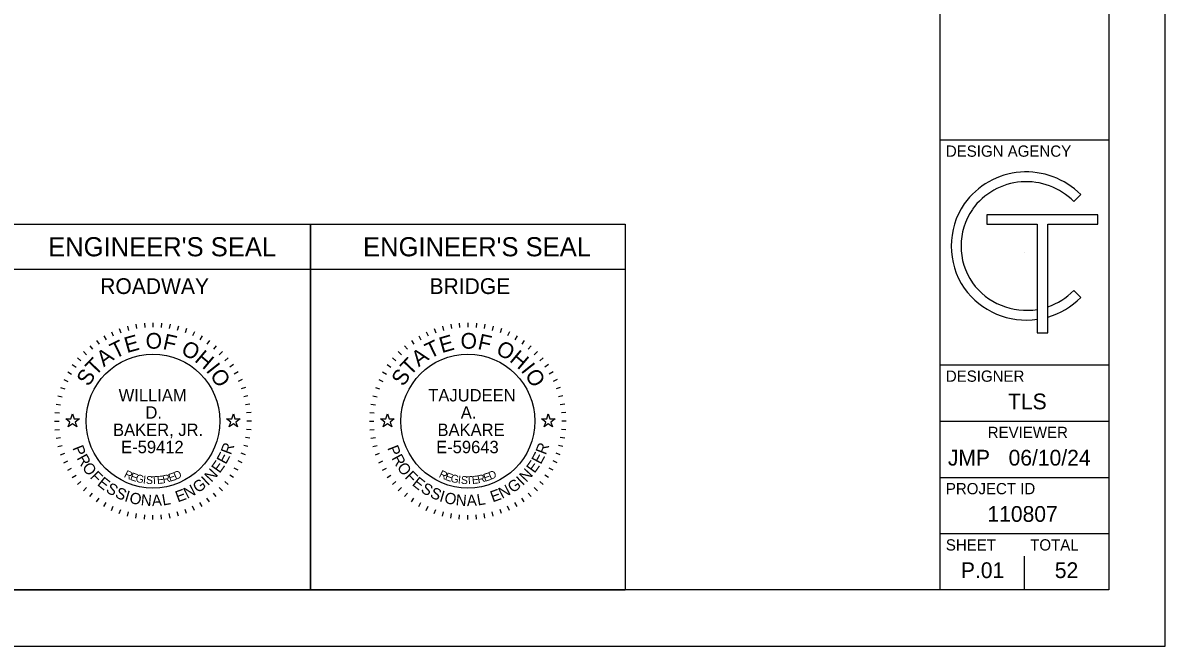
# Model space of a CAD drawing. Extents: x -5.4 to 71.3, y -12 to 22.
# Drawn here: x 23.84 to 34, y 0 to 5.54 of the extents above; entities that cross this region are included whole.
import ezdxf

# ---------------------------------------------------------------- set-up
doc = ezdxf.new("R2010")
doc.units = 0
for name, color, linetype in [('Default', 7, 'Continuous'), ('SH_Border', 7, 'Continuous'), ('SH_Cut_Line', 7, 'Continuous'), ('SH_Data', 7, 'Continuous'), ('SH_Text', 7, 'Continuous')]:
    doc.layers.add(name, color=color, linetype=linetype)

msp = doc.modelspace()

# ---------------------------------------------------------------- linework, layer by layer
at = {"layer": 'Default'}
for points in [[(24.224, 2.02), (24.271, 2.02), (24.285, 2.065), (24.299, 2.02), (24.346, 2.02), (24.308, 1.992), (24.323, 1.948), (24.285, 1.975), (24.247, 1.948), (24.262, 1.992)], [(25.654, 2.02), (25.701, 2.02), (25.715, 2.065), (25.729, 2.02), (25.776, 2.02), (25.738, 1.992), (25.753, 1.948), (25.715, 1.975), (25.677, 1.948), (25.692, 1.992)], [(27.024, 2.02), (27.071, 2.02), (27.085, 2.065), (27.099, 2.02), (27.146, 2.02), (27.108, 1.992), (27.123, 1.948), (27.085, 1.975), (27.047, 1.948), (27.062, 1.992)], [(28.454, 2.02), (28.501, 2.02), (28.515, 2.065), (28.529, 2.02), (28.576, 2.02), (28.538, 1.992), (28.553, 1.948), (28.515, 1.975), (28.477, 1.948), (28.492, 1.992)]]:
    msp.add_lwpolyline(points, close=True, dxfattribs=at)
at = {"layer": 'SH_Border'}
for p, q in [((32, 0.5), (32, 21.5)), ((32, 4.5), (33.5, 4.5)), ((32, 2.5), (33.5, 2.5)), ((32, 2), (33.5, 2)), ((32, 1.5), (33.5, 1.5)), ((32, 1), (33.5, 1))]:
    msp.add_line(p, q, dxfattribs=at)
msp.add_lwpolyline([(1.5, 21.5), (33.5, 21.5), (33.5, 0.5), (1.5, 0.5)], close=True, dxfattribs=at)
at = {"layer": 'SH_Cut_Line'}
msp.add_lwpolyline([(0, 0), (34, 0), (34, 22), (0, 22)], close=True, dxfattribs=at)
at = {"layer": 'SH_Data'}
for p, q in [((23.6, 3.75), (26.4, 3.75)), ((26.4, 3.75), (26.4, 0.5)), ((26.4, 0.5), (26.4, 3.75)), ((26.4, 3.75), (29.2, 3.75)), ((29.2, 3.75), (29.2, 0.5)), ((32.75, 3.5), (32.75, 3.5)), ((23.6, 3.35), (26.4, 3.35)), ((26.4, 3.35), (29.2, 3.35)), ((24.774, 2.845), (24.784, 2.807)), ((24.848, 2.862), (24.855, 2.822)), ((24.924, 2.872), (24.927, 2.832)), ((25, 2.875), (25, 2.835)), ((25.076, 2.872), (25.073, 2.832)), ((25.152, 2.862), (25.145, 2.822)), ((25.226, 2.845), (25.216, 2.807)), ((27.574, 2.845), (27.584, 2.807)), ((27.648, 2.862), (27.655, 2.822)), ((27.724, 2.872), (27.727, 2.832)), ((27.8, 2.875), (27.8, 2.835)), ((27.876, 2.872), (27.873, 2.832)), ((27.952, 2.862), (27.945, 2.822)), ((28.026, 2.845), (28.016, 2.807)), ((24.563, 2.758), (24.583, 2.723)), ((24.63, 2.793), (24.647, 2.757)), ((24.701, 2.822), (24.714, 2.785)), ((25.299, 2.822), (25.286, 2.785)), ((25.37, 2.793), (25.353, 2.757)), ((25.437, 2.758), (25.417, 2.723)), ((27.363, 2.758), (27.383, 2.723)), ((27.43, 2.793), (27.447, 2.757)), ((27.501, 2.822), (27.514, 2.785)), ((28.099, 2.822), (28.086, 2.785)), ((28.17, 2.793), (28.153, 2.757)), ((28.237, 2.758), (28.217, 2.723)), ((24.438, 2.67), (24.463, 2.64)), ((24.498, 2.717), (24.521, 2.684)), ((25.502, 2.717), (25.479, 2.684)), ((25.562, 2.67), (25.537, 2.64)), ((27.238, 2.67), (27.263, 2.64)), ((27.298, 2.717), (27.321, 2.684)), ((28.302, 2.717), (28.279, 2.684)), ((28.362, 2.67), (28.337, 2.64)), ((24.33, 2.562), (24.36, 2.537)), ((24.381, 2.619), (24.41, 2.59)), ((25.619, 2.619), (25.59, 2.59)), ((25.67, 2.562), (25.64, 2.537)), ((27.13, 2.562), (27.16, 2.537)), ((27.181, 2.619), (27.21, 2.59)), ((28.419, 2.619), (28.39, 2.59)), ((28.47, 2.562), (28.44, 2.537)), ((24.283, 2.502), (24.316, 2.479)), ((25.717, 2.502), (25.684, 2.479)), ((27.083, 2.502), (27.116, 2.479)), ((28.517, 2.502), (28.484, 2.479)), ((24.207, 2.37), (24.243, 2.353)), ((24.242, 2.438), (24.277, 2.418)), ((25.758, 2.438), (25.723, 2.418)), ((25.793, 2.37), (25.757, 2.353)), ((27.007, 2.37), (27.043, 2.353)), ((27.042, 2.438), (27.077, 2.418)), ((28.558, 2.438), (28.523, 2.418)), ((28.593, 2.37), (28.557, 2.353)), ((24.178, 2.299), (24.215, 2.286)), ((25.822, 2.299), (25.785, 2.286)), ((26.978, 2.299), (27.015, 2.286)), ((28.622, 2.299), (28.585, 2.286)), ((24.138, 2.152), (24.178, 2.145)), ((24.155, 2.226), (24.193, 2.216)), ((25.845, 2.226), (25.807, 2.216)), ((25.862, 2.152), (25.822, 2.145)), ((26.938, 2.152), (26.978, 2.145)), ((26.955, 2.226), (26.993, 2.216)), ((28.645, 2.226), (28.607, 2.216)), ((28.662, 2.152), (28.622, 2.145)), ((24.128, 2.076), (24.168, 2.073)), ((25.872, 2.076), (25.832, 2.073)), ((26.928, 2.076), (26.968, 2.073)), ((28.672, 2.076), (28.632, 2.073)), ((24.125, 2), (24.165, 2)), ((25.875, 2), (25.835, 2)), ((26.925, 2), (26.965, 2)), ((28.675, 2), (28.635, 2)), ((24.128, 1.924), (24.168, 1.927)), ((24.138, 1.848), (24.178, 1.855)), ((25.862, 1.848), (25.822, 1.855)), ((25.872, 1.924), (25.832, 1.927)), ((26.928, 1.924), (26.968, 1.927)), ((26.938, 1.848), (26.978, 1.855)), ((28.662, 1.848), (28.622, 1.855)), ((28.672, 1.924), (28.632, 1.927)), ((24.155, 1.774), (24.193, 1.784)), ((25.845, 1.774), (25.807, 1.784)), ((26.955, 1.774), (26.993, 1.784)), ((28.645, 1.774), (28.607, 1.784)), ((24.178, 1.701), (24.215, 1.714)), ((24.207, 1.63), (24.243, 1.647)), ((25.793, 1.63), (25.757, 1.647)), ((25.822, 1.701), (25.785, 1.714)), ((26.978, 1.701), (27.015, 1.714)), ((27.007, 1.63), (27.043, 1.647)), ((28.593, 1.63), (28.557, 1.647)), ((28.622, 1.701), (28.585, 1.714)), ((24.242, 1.563), (24.277, 1.583)), ((25.758, 1.563), (25.723, 1.583)), ((27.042, 1.563), (27.077, 1.583)), ((28.558, 1.563), (28.523, 1.583)), ((24.283, 1.498), (24.316, 1.521)), ((24.33, 1.438), (24.36, 1.463)), ((25.67, 1.438), (25.64, 1.463)), ((25.717, 1.498), (25.684, 1.521)), ((27.083, 1.498), (27.116, 1.521)), ((27.13, 1.438), (27.16, 1.463)), ((28.47, 1.438), (28.44, 1.463)), ((28.517, 1.498), (28.484, 1.521)), ((24.381, 1.381), (24.41, 1.41)), ((24.438, 1.33), (24.463, 1.36)), ((25.562, 1.33), (25.537, 1.36)), ((25.619, 1.381), (25.59, 1.41)), ((27.181, 1.381), (27.21, 1.41)), ((27.238, 1.33), (27.263, 1.36)), ((28.362, 1.33), (28.337, 1.36)), ((28.419, 1.381), (28.39, 1.41)), ((24.498, 1.283), (24.521, 1.316)), ((24.563, 1.242), (24.583, 1.277)), ((24.63, 1.207), (24.647, 1.243)), ((25.37, 1.207), (25.353, 1.243)), ((25.437, 1.242), (25.417, 1.277)), ((25.502, 1.283), (25.479, 1.316)), ((27.298, 1.283), (27.321, 1.316)), ((27.363, 1.242), (27.383, 1.277)), ((27.43, 1.207), (27.447, 1.243)), ((28.17, 1.207), (28.153, 1.243)), ((28.237, 1.242), (28.217, 1.277)), ((28.302, 1.283), (28.279, 1.316)), ((24.701, 1.178), (24.714, 1.215)), ((24.774, 1.155), (24.784, 1.193)), ((24.848, 1.138), (24.855, 1.178)), ((24.924, 1.128), (24.927, 1.168)), ((25, 1.125), (25, 1.165)), ((25.076, 1.128), (25.073, 1.168)), ((25.152, 1.138), (25.145, 1.178)), ((25.226, 1.155), (25.216, 1.193)), ((25.299, 1.178), (25.286, 1.215)), ((27.501, 1.178), (27.514, 1.215)), ((27.574, 1.155), (27.584, 1.193)), ((27.648, 1.138), (27.655, 1.178)), ((27.724, 1.128), (27.727, 1.168)), ((27.8, 1.125), (27.8, 1.165)), ((27.876, 1.128), (27.873, 1.168)), ((27.952, 1.138), (27.945, 1.178)), ((28.026, 1.155), (28.016, 1.193)), ((28.099, 1.178), (28.086, 1.215)), ((32.75, 0.5), (32.75, 0.8)), ((32.375, 0.675), (32.375, 0.675)), ((23.6, 0.5), (26.4, 0.5)), ((23.6, 0.5), (26.4, 0.5)), ((26.4, 0.5), (29.2, 0.5)), ((26.4, 0.5), (29.2, 0.5))]:
    msp.add_line(p, q, dxfattribs=at)
for centre in [(25, 2), (27.8, 2)]:
    msp.add_circle(centre, 0.595, dxfattribs=at)
at = {"layer": 'SH_Text'}
for p, q in [((33.249, 4.013), (33.187, 3.952)), ((33.249, 4.013), (33.187, 3.952)), ((33.402, 3.833), (32.414, 3.833)), ((32.414, 3.833), (32.414, 3.751)), ((33.402, 3.751), (33.402, 3.833)), ((32.414, 3.751), (32.863, 3.751)), ((32.863, 3.751), (32.863, 2.785)), ((32.956, 2.785), (32.956, 3.751)), ((32.956, 3.751), (33.402, 3.751)), ((33.187, 3.16), (33.249, 3.099)), ((33.187, 3.16), (33.249, 3.099)), ((32.863, 2.993), (32.863, 2.905)), ((32.863, 2.993), (32.863, 2.905)), ((32.956, 2.925), (32.956, 3.016)), ((32.956, 2.925), (32.956, 3.016)), ((32.863, 2.785), (32.956, 2.785))]:
    msp.add_line(p, q, dxfattribs=at)
msp.add_lwpolyline([(32.863, 3.751), (32.863, 2.785), (32.956, 2.785), (32.956, 3.751), (33.402, 3.751), (33.402, 3.833), (32.414, 3.833), (32.414, 3.751)], close=True, dxfattribs=at)
for centre, radius, start, end in [((32.766, 3.535), 0.68, 44.7027, 144.3276), ((32.766, 3.535), 0.68, 44.7027, 144.3276), ((32.766, 3.535), 0.593, 44.7362, 144.1102), ((32.766, 3.535), 0.593, 44.7362, 144.1102), ((32.764, 3.556), 0.666, 145.7329, 214.2671), ((32.764, 3.556), 0.666, 145.7329, 214.2671), ((32.764, 3.556), 0.579, 145.7266, 214.2734), ((32.764, 3.556), 0.579, 145.7266, 214.2734), ((32.766, 3.578), 0.68, 215.6724, 278.2613), ((32.766, 3.578), 0.68, 215.6724, 278.2613), ((32.766, 3.578), 0.593, 215.8898, 279.4882), ((32.766, 3.578), 0.593, 215.8898, 279.4882), ((32.766, 3.578), 0.593, 288.6992, 315.2638), ((32.766, 3.578), 0.593, 288.6992, 315.2638), ((32.766, 3.578), 0.68, 286.2291, 315.2973), ((32.766, 3.578), 0.68, 286.2291, 315.2973)]:
    msp.add_arc(centre, radius, start, end, dxfattribs=at)

# ---------------------------------------------------------------- texts
at = {"layer": 'SH_Data'}
for s, height, p in [('DESIGN AGENCY', 0.1, (32.05, 4.35)), ("ENGINEER'S SEAL", 0.17, (24.068, 3.465)), ("ENGINEER'S SEAL", 0.17, (26.868, 3.465)), ('ROADWAY', 0.14, (24.531, 3.13)), ('BRIDGE', 0.14, (27.459, 3.13)), ('DESIGNER', 0.1, (32.05, 2.35)), ('WILLIAM', 0.11, (24.695, 2.175)), ('TAJUDEEN', 0.11, (27.448, 2.175)), ('TLS', 0.14, (32.603, 2.105)), ('D.', 0.11, (24.933, 2.022)), ('A.', 0.11, (27.737, 2.022)), ('BAKER, JR.', 0.11, (24.645, 1.868)), ('BAKARE', 0.11, (27.53, 1.868)), ('REVIEWER', 0.1, (32.422, 1.85)), ('E-59412', 0.11, (24.717, 1.715)), ('E-59643', 0.11, (27.518, 1.715)), ('JMP', 0.14, (32.068, 1.605)), ('06/10/24', 0.14, (32.608, 1.605)), ('PROJECT ID', 0.1, (32.05, 1.35)), ('110807', 0.14, (32.42, 1.105)), ('SHEET', 0.1, (32.05, 0.85)), ('TOTAL', 0.1, (32.8, 0.85)), ('P.01', 0.14, (32.184, 0.605)), ('52', 0.14, (33.019, 0.605))]:
    msp.add_text(s, height=height, dxfattribs=at).set_placement(p)
for s, height, rotation, p in [('E', 0.14, 15.7571, (24.768, 2.604)), ('O', 0.14, 359.7812, (24.935, 2.644)), ('F', 0.14, 347.4362, (25.081, 2.642)), ('E', 0.14, 15.7571, (27.568, 2.604)), ('O', 0.14, 359.7812, (27.735, 2.644)), ('F', 0.14, 347.4362, (27.881, 2.642)), ('T', 0.14, 25.7167, (24.662, 2.552)), ('O', 0.14, 332.2586, (25.24, 2.602)), ('T', 0.14, 25.7167, (27.462, 2.552)), ('O', 0.14, 332.2586, (28.04, 2.602)), ('T', 0.14, 46.4344, (24.488, 2.396)), ('A', 0.14, 36.4747, (24.563, 2.478)), ('H', 0.14, 319.9136, (25.363, 2.536)), ('T', 0.14, 46.4344, (27.288, 2.396)), ('A', 0.14, 36.4747, (27.363, 2.478)), ('H', 0.14, 319.9136, (28.163, 2.536)), ('S', 0.14, 57.1924, (24.428, 2.301)), ('I', 0.14, 308.367, (25.466, 2.448)), ('O', 0.14, 303.1491, (25.502, 2.409)), ('S', 0.14, 57.1924, (27.228, 2.301)), ('I', 0.14, 308.367, (28.266, 2.448)), ('O', 0.14, 303.1491, (28.302, 2.409)), ('P', 0.1, 291.494, (24.282, 1.762)), ('E', 0.1, 61.9951, (25.648, 1.61)), ('R', 0.1, 69.2322, (25.692, 1.695)), ('P', 0.1, 291.494, (27.082, 1.762)), ('E', 0.1, 61.9951, (28.448, 1.61)), ('R', 0.1, 69.2322, (28.492, 1.695)), ('R', 0.1, 298.7311, (24.319, 1.672)), ('O', 0.1, 306.4666, (24.365, 1.588)), ('E', 0.1, 54.758, (25.593, 1.531)), ('R', 0.1, 298.7311, (27.119, 1.672)), ('O', 0.1, 306.4666, (27.165, 1.588)), ('E', 0.1, 54.758, (28.393, 1.531)), ('F', 0.1, 314.7068, (24.434, 1.498)), ('R', 0.07, 334.487, (24.737, 1.505)), ('E', 0.07, 341.04, (24.791, 1.48)), ('G', 0.07, 347.4752, (24.841, 1.462)), ('R', 0.07, 11.9184, (25.092, 1.447)), ('E', 0.07, 17.6836, (25.15, 1.46)), ('D', 0.07, 23.3052, (25.201, 1.477)), ('N', 0.1, 47.0224, (25.52, 1.451)), ('F', 0.1, 314.7068, (27.234, 1.498)), ('R', 0.07, 334.487, (27.537, 1.505)), ('E', 0.07, 341.04, (27.591, 1.48)), ('G', 0.07, 347.4752, (27.641, 1.462)), ('R', 0.07, 11.9184, (27.892, 1.447)), ('E', 0.07, 17.6836, (27.95, 1.46)), ('D', 0.07, 23.3052, (28.001, 1.477)), ('N', 0.1, 47.0224, (28.32, 1.451)), ('E', 0.1, 321.4393, (24.498, 1.435)), ('S', 0.1, 328.6764, (24.574, 1.375)), ('I', 0.07, 353.7858, (24.909, 1.447)), ('S', 0.07, 356.8926, (24.936, 1.443)), ('T', 0.07, 3.0061, (24.986, 1.439)), ('E', 0.07, 6.0117, (25.039, 1.441)), ('N', 0.1, 27.3113, (25.304, 1.308)), ('G', 0.1, 35.0469, (25.398, 1.357)), ('I', 0.1, 43.287, (25.487, 1.421)), ('E', 0.1, 321.4393, (27.298, 1.435)), ('S', 0.1, 328.6764, (27.374, 1.375)), ('I', 0.07, 353.7858, (27.709, 1.447)), ('S', 0.07, 356.8926, (27.736, 1.443)), ('T', 0.07, 3.0061, (27.786, 1.439)), ('E', 0.07, 6.0117, (27.839, 1.441)), ('N', 0.1, 27.3113, (28.104, 1.308)), ('G', 0.1, 35.0469, (28.198, 1.357)), ('I', 0.1, 43.287, (28.287, 1.421)), ('S', 0.1, 335.9134, (24.656, 1.327)), ('I', 0.1, 343.1505, (24.741, 1.29)), ('O', 0.1, 346.8859, (24.784, 1.275)), ('N', 0.1, 355.1261, (24.889, 1.252)), ('A', 0.1, 2.8617, (24.992, 1.244)), ('L', 0.1, 10.0987, (25.089, 1.249)), ('E', 0.1, 20.0742, (25.221, 1.277)), ('S', 0.1, 335.9134, (27.456, 1.327)), ('I', 0.1, 343.1505, (27.541, 1.29)), ('O', 0.1, 346.8859, (27.584, 1.275)), ('N', 0.1, 355.1261, (27.689, 1.252)), ('A', 0.1, 2.8617, (27.792, 1.244)), ('L', 0.1, 10.0987, (27.889, 1.249)), ('E', 0.1, 20.0742, (28.021, 1.277))]:
    msp.add_text(s, height=height, rotation=rotation, dxfattribs=at).set_placement(p)

doc.saveas('drawing.dxf')
